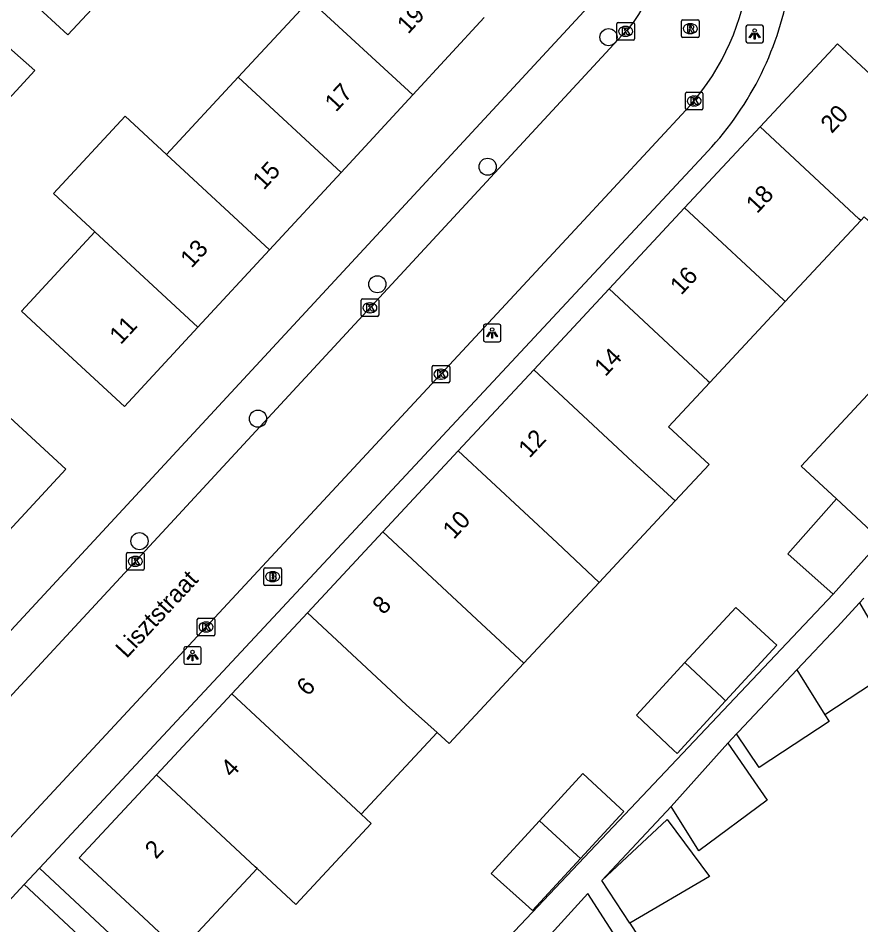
# Model space of a CAD drawing. Extents: x 159222 to 160346, y 381249 to 382166.
# Drawn here: x 159950.6 to 159998.6, y 381636 to 381687.7 of the extents above; entities that cross this region are included whole.
import ezdxf

# ---------------------------------------------------------------- set-up
doc = ezdxf.new("R2010")
doc.units = 0
for name, color, linetype in [('IMGEO_Boom', 7, 'Continuous'), ('IMGEO_Brandkraan', 7, 'Continuous'), ('IMGEO_Kolk', 7, 'Continuous'), ('IMGEO_Lichtpunt', 7, 'Continuous'), ('IMGEO_Openbare_ruimte_label', 7, 'Continuous'), ('IMGEO_Pand', 7, 'Continuous'), ('IMGEO_Pand_nummerreeks', 7, 'Continuous'), ('IMGEO_Rijbaan_lokaal_open', 7, 'Continuous'), ('IMGEO_Rioolput', 7, 'Continuous'), ('IMGEO_Voetpad_open', 7, 'Continuous')]:
    doc.layers.add(name, color=color, linetype=linetype)

msp = doc.modelspace()

# ---------------------------------------------------------------- linework, layer by layer
at = {"layer": 'IMGEO_Boom'}
for centre in [(159984.255, 381686.602), (159977.364, 381679.218), (159971.081, 381672.52), (159964.278, 381664.857), (159957.526, 381657.879)]:
    msp.add_circle(centre, 0.489, dxfattribs=at)
at = {"layer": 'IMGEO_Brandkraan'}
for p, q in [((159964.615, 381655.428), (159964.615, 381656.28)), ((159964.69, 381656.354), (159965.542, 381656.354)), ((159965.103, 381656.134), (159965.128, 381656.134)), ((159965.616, 381656.28), (159965.616, 381655.428)), ((159965.126, 381655.574), (159965.101, 381655.574)), ((159965.542, 381655.354), (159964.69, 381655.354))]:
    msp.add_line(p, q, dxfattribs=at)
for points in [[(159964.615, 381655.428), (159964.615, 381656.28)], [(159964.69, 381656.354), (159965.542, 381656.354)], [(159964.963, 381656.054), (159964.963, 381655.654), (159965.176, 381655.654)], [(159965.194, 381656.054), (159964.963, 381656.054)], [(159965.142, 381655.973), (159965.088, 381655.973), (159965.088, 381655.897)], [(159965.616, 381656.28), (159965.616, 381655.428)], [(159965.088, 381655.897), (159965.141, 381655.897)], [(159965.15, 381655.821), (159965.088, 381655.821), (159965.088, 381655.74)], [(159965.088, 381655.74), (159965.15, 381655.74)], [(159965.542, 381655.354), (159964.69, 381655.354)]]:
    msp.add_lwpolyline(points, dxfattribs=at)
for centre, radius, start, end in [((159964.692, 381656.278), 0.0765, 91.552, 178.448), ((159964.692, 381656.278), 0.0765, 91.552, 178.448), ((159965.143, 381655.935), 0.0379, 267.8285, 90.9355), ((159965.198, 381655.909), 0.145, 59.4692, 91.5367), ((159965.223, 381655.956), 0.0922, 285.5137, 58.1501), ((159965.54, 381656.278), 0.0765, 1.552, 88.448), ((159965.54, 381656.278), 0.0765, 1.552, 88.448), ((159964.692, 381655.43), 0.0765, 181.552, 268.448), ((159964.692, 381655.43), 0.0765, 181.552, 268.448), ((159965.151, 381655.78), 0.0404, 269.8759, 90.5077), ((159965.182, 381655.905), 0.251, 268.6676, 293.5347), ((159965.228, 381655.764), 0.105, 301.3115, 78.989), ((159965.54, 381655.43), 0.0765, 271.552, 358.448), ((159965.54, 381655.43), 0.0765, 271.552, 358.448)]:
    msp.add_arc(centre, radius, start, end, dxfattribs=at)
for centre, major_axis, ratio, start_param, end_param in [((159965.102, 381655.854), (-0.387, 0.002), 0.722429, 4.712389, 7.853982), ((159965.127, 381655.854), (-0.39, 0.002), 0.717154, 1.570796, 4.712389)]:
    msp.add_ellipse(centre, major_axis=major_axis, ratio=ratio, start_param=start_param, end_param=end_param, dxfattribs=at)
at = {"layer": 'IMGEO_Kolk'}
for p, q in [((159984.728, 381686.511), (159984.728, 381687.363)), ((159984.803, 381687.437), (159985.655, 381687.437)), ((159985.216, 381687.217), (159985.241, 381687.217)), ((159985.729, 381687.363), (159985.729, 381686.511)), ((159985.655, 381686.437), (159984.803, 381686.437)), ((159985.239, 381686.657), (159985.214, 381686.657)), ((159988.633, 381682.536), (159988.633, 381683.388)), ((159988.708, 381683.462), (159989.56, 381683.462)), ((159989.634, 381683.388), (159989.634, 381682.536)), ((159989.121, 381683.242), (159989.146, 381683.242)), ((159989.56, 381682.462), (159988.708, 381682.462)), ((159989.144, 381682.682), (159989.119, 381682.682)), ((159970.156, 381670.754), (159970.156, 381671.606)), ((159970.231, 381671.68), (159971.083, 381671.68)), ((159970.644, 381671.46), (159970.669, 381671.46)), ((159971.157, 381671.606), (159971.157, 381670.754)), ((159971.083, 381670.68), (159970.231, 381670.68)), ((159970.667, 381670.9), (159970.642, 381670.9)), ((159974.276, 381667.896), (159975.128, 381667.896)), ((159974.201, 381666.97), (159974.201, 381667.822)), ((159974.689, 381667.676), (159974.714, 381667.676)), ((159975.202, 381667.822), (159975.202, 381666.97)), ((159975.128, 381666.896), (159974.276, 381666.896)), ((159974.712, 381667.116), (159974.687, 381667.116)), ((159956.79, 381656.3), (159956.79, 381657.152)), ((159956.865, 381657.226), (159957.717, 381657.226)), ((159957.278, 381657.006), (159957.303, 381657.006)), ((159957.791, 381657.152), (159957.791, 381656.3)), ((159957.717, 381656.226), (159956.865, 381656.226)), ((159957.301, 381656.446), (159957.276, 381656.446)), ((159960.821, 381652.56), (159960.821, 381653.412)), ((159960.896, 381653.486), (159961.748, 381653.486)), ((159961.822, 381653.412), (159961.822, 381652.56)), ((159961.309, 381653.266), (159961.334, 381653.266)), ((159961.748, 381652.486), (159960.896, 381652.486)), ((159961.332, 381652.706), (159961.307, 381652.706))]:
    msp.add_line(p, q, dxfattribs=at)
for points in [[(159984.728, 381686.511), (159984.728, 381687.363)], [(159984.803, 381687.437), (159985.655, 381687.437)], [(159985.049, 381687.137), (159985.172, 381687.137), (159985.172, 381686.986), (159985.302, 381687.137), (159985.466, 381687.137), (159985.32, 381686.986), (159985.473, 381686.737), (159985.321, 381686.737), (159985.236, 381686.901), (159985.172, 381686.834), (159985.172, 381686.737), (159985.049, 381686.737), (159985.049, 381687.137)], [(159985.729, 381687.363), (159985.729, 381686.511)], [(159985.655, 381686.437), (159984.803, 381686.437)], [(159988.633, 381682.536), (159988.633, 381683.388)], [(159988.708, 381683.462), (159989.56, 381683.462)], [(159989.634, 381683.388), (159989.634, 381682.536)], [(159988.954, 381683.162), (159989.077, 381683.162), (159989.077, 381683.011), (159989.207, 381683.162), (159989.371, 381683.162), (159989.225, 381683.011), (159989.378, 381682.762), (159989.226, 381682.762), (159989.141, 381682.926), (159989.077, 381682.859), (159989.077, 381682.762), (159988.954, 381682.762), (159988.954, 381683.162)], [(159989.56, 381682.462), (159988.708, 381682.462)], [(159970.156, 381670.754), (159970.156, 381671.606)], [(159970.231, 381671.68), (159971.083, 381671.68)], [(159971.157, 381671.606), (159971.157, 381670.754)], [(159970.477, 381671.38), (159970.6, 381671.38), (159970.6, 381671.229), (159970.73, 381671.38), (159970.894, 381671.38), (159970.748, 381671.229), (159970.901, 381670.98), (159970.749, 381670.98), (159970.664, 381671.144), (159970.6, 381671.077), (159970.6, 381670.98), (159970.477, 381670.98), (159970.477, 381671.38)], [(159971.083, 381670.68), (159970.231, 381670.68)], [(159974.276, 381667.896), (159975.128, 381667.896)], [(159974.201, 381666.97), (159974.201, 381667.822)], [(159974.522, 381667.596), (159974.645, 381667.596), (159974.645, 381667.445), (159974.775, 381667.596), (159974.939, 381667.596), (159974.793, 381667.445), (159974.946, 381667.196), (159974.794, 381667.196), (159974.709, 381667.36), (159974.645, 381667.293), (159974.645, 381667.196), (159974.522, 381667.196), (159974.522, 381667.596)], [(159975.202, 381667.822), (159975.202, 381666.97)], [(159975.128, 381666.896), (159974.276, 381666.896)], [(159956.79, 381656.3), (159956.79, 381657.152)], [(159956.865, 381657.226), (159957.717, 381657.226)], [(159957.791, 381657.152), (159957.791, 381656.3)], [(159957.111, 381656.926), (159957.234, 381656.926), (159957.234, 381656.775), (159957.364, 381656.926), (159957.528, 381656.926), (159957.382, 381656.775), (159957.535, 381656.526), (159957.383, 381656.526), (159957.298, 381656.69), (159957.234, 381656.623), (159957.234, 381656.526), (159957.111, 381656.526), (159957.111, 381656.926)], [(159957.717, 381656.226), (159956.865, 381656.226)], [(159960.821, 381652.56), (159960.821, 381653.412)], [(159960.896, 381653.486), (159961.748, 381653.486)], [(159961.822, 381653.412), (159961.822, 381652.56)], [(159961.142, 381653.186), (159961.265, 381653.186), (159961.265, 381653.035), (159961.395, 381653.186), (159961.559, 381653.186), (159961.413, 381653.035), (159961.566, 381652.786), (159961.414, 381652.786), (159961.329, 381652.95), (159961.265, 381652.883), (159961.265, 381652.786), (159961.142, 381652.786), (159961.142, 381653.186)], [(159961.748, 381652.486), (159960.896, 381652.486)]]:
    msp.add_lwpolyline(points, dxfattribs=at)
for centre, start, end in [((159984.805, 381687.361), 91.552, 178.448), ((159984.805, 381687.361), 91.552, 178.448), ((159985.653, 381687.361), 1.552, 88.448), ((159985.653, 381687.361), 1.552, 88.448), ((159984.805, 381686.513), 181.552, 268.448), ((159984.805, 381686.513), 181.552, 268.448), ((159985.653, 381686.513), 271.552, 358.448), ((159985.653, 381686.513), 271.552, 358.448), ((159988.71, 381683.386), 91.552, 178.448), ((159988.71, 381683.386), 91.552, 178.448), ((159989.558, 381683.386), 1.552, 88.448), ((159989.558, 381683.386), 1.552, 88.448), ((159988.71, 381682.538), 181.552, 268.448), ((159988.71, 381682.538), 181.552, 268.448), ((159989.558, 381682.538), 271.552, 358.448), ((159989.558, 381682.538), 271.552, 358.448), ((159970.233, 381671.604), 91.552, 178.448), ((159970.233, 381671.604), 91.552, 178.448), ((159971.081, 381671.604), 1.552, 88.448), ((159971.081, 381671.604), 1.552, 88.448), ((159970.233, 381670.756), 181.552, 268.448), ((159970.233, 381670.756), 181.552, 268.448), ((159971.081, 381670.756), 271.552, 358.448), ((159971.081, 381670.756), 271.552, 358.448), ((159974.278, 381667.82), 91.552, 178.448), ((159974.278, 381667.82), 91.552, 178.448), ((159975.126, 381667.82), 1.552, 88.448), ((159975.126, 381667.82), 1.552, 88.448), ((159974.278, 381666.972), 181.552, 268.448), ((159974.278, 381666.972), 181.552, 268.448), ((159975.126, 381666.972), 271.552, 358.448), ((159975.126, 381666.972), 271.552, 358.448), ((159956.867, 381657.15), 91.552, 178.448), ((159956.867, 381657.15), 91.552, 178.448), ((159957.715, 381657.15), 1.552, 88.448), ((159957.715, 381657.15), 1.552, 88.448), ((159956.867, 381656.302), 181.552, 268.448), ((159956.867, 381656.302), 181.552, 268.448), ((159957.715, 381656.302), 271.552, 358.448), ((159957.715, 381656.302), 271.552, 358.448), ((159960.898, 381653.41), 91.552, 178.448), ((159960.898, 381653.41), 91.552, 178.448), ((159961.746, 381653.41), 1.552, 88.448), ((159961.746, 381653.41), 1.552, 88.448), ((159960.898, 381652.562), 181.552, 268.448), ((159960.898, 381652.562), 181.552, 268.448), ((159961.746, 381652.562), 271.552, 358.448), ((159961.746, 381652.562), 271.552, 358.448)]:
    msp.add_arc(centre, 0.0765, start, end, dxfattribs=at)
for centre, major_axis, ratio, start_param, end_param in [((159985.215, 381686.937), (-0.387, 0.002), 0.722429, 4.712389, 7.853982), ((159985.24, 381686.937), (-0.39, 0.002), 0.717154, 1.570796, 4.712389), ((159989.12, 381682.962), (-0.387, 0.002), 0.722429, 4.712389, 7.853982), ((159989.145, 381682.962), (-0.39, 0.002), 0.717154, 1.570796, 4.712389), ((159970.643, 381671.18), (-0.387, 0.002), 0.722429, 4.712389, 7.853982), ((159970.668, 381671.18), (-0.39, 0.002), 0.717154, 1.570796, 4.712389), ((159974.688, 381667.396), (-0.387, 0.002), 0.722429, 4.712389, 7.853982), ((159974.713, 381667.396), (-0.39, 0.002), 0.717154, 1.570796, 4.712389), ((159957.277, 381656.726), (-0.387, 0.002), 0.722429, 4.712389, 7.853982), ((159957.302, 381656.726), (-0.39, 0.002), 0.717154, 1.570796, 4.712389), ((159961.308, 381652.986), (-0.387, 0.002), 0.722429, 4.712389, 7.853982), ((159961.333, 381652.986), (-0.39, 0.002), 0.717154, 1.570796, 4.712389)]:
    msp.add_ellipse(centre, major_axis=major_axis, ratio=ratio, start_param=start_param, end_param=end_param, dxfattribs=at)
at = {"layer": 'IMGEO_Lichtpunt'}
for p, q in [((159992.081, 381687.188), (159992.081, 381686.381)), ((159992.081, 381687.188), (159992.081, 381686.381)), ((159992.983, 381687.283), (159992.175, 381687.283)), ((159992.983, 381687.283), (159992.175, 381687.283)), ((159993.077, 381686.381), (159993.077, 381687.188)), ((159993.077, 381686.381), (159993.077, 381687.188)), ((159992.175, 381686.287), (159992.983, 381686.287)), ((159992.175, 381686.287), (159992.983, 381686.287)), ((159977.124, 381670.146), (159977.124, 381669.339)), ((159977.124, 381670.146), (159977.124, 381669.339)), ((159978.026, 381670.241), (159977.218, 381670.241)), ((159978.026, 381670.241), (159977.218, 381670.241)), ((159978.12, 381669.339), (159978.12, 381670.146)), ((159978.12, 381669.339), (159978.12, 381670.146)), ((159977.218, 381669.245), (159978.026, 381669.245)), ((159977.218, 381669.245), (159978.026, 381669.245)), ((159960.954, 381651.855), (159960.146, 381651.855)), ((159960.954, 381651.855), (159960.146, 381651.855)), ((159960.052, 381651.76), (159960.052, 381650.953)), ((159960.052, 381651.76), (159960.052, 381650.953)), ((159961.048, 381650.953), (159961.048, 381651.76)), ((159961.048, 381650.953), (159961.048, 381651.76)), ((159960.146, 381650.859), (159960.954, 381650.859)), ((159960.146, 381650.859), (159960.954, 381650.859))]:
    msp.add_line(p, q, dxfattribs=at)
for points in [[(159992.455, 381686.852), (159992.494, 381686.824), (159992.306, 381686.562), (159992.268, 381686.589), (159992.455, 381686.852)], [(159992.557, 381686.804), (159992.604, 381686.804), (159992.604, 381686.482), (159992.557, 381686.482), (159992.557, 381686.804)], [(159992.667, 381686.824), (159992.705, 381686.851), (159992.892, 381686.589), (159992.853, 381686.561), (159992.667, 381686.824)], [(159977.498, 381669.81), (159977.537, 381669.782), (159977.349, 381669.52), (159977.311, 381669.547), (159977.498, 381669.81)], [(159977.6, 381669.762), (159977.647, 381669.762), (159977.647, 381669.44), (159977.6, 381669.44), (159977.6, 381669.762)], [(159977.71, 381669.782), (159977.748, 381669.809), (159977.935, 381669.547), (159977.896, 381669.519), (159977.71, 381669.782)], [(159960.426, 381651.424), (159960.465, 381651.396), (159960.277, 381651.134), (159960.239, 381651.161), (159960.426, 381651.424)], [(159960.528, 381651.376), (159960.575, 381651.376), (159960.575, 381651.054), (159960.528, 381651.054), (159960.528, 381651.376)], [(159960.638, 381651.396), (159960.676, 381651.423), (159960.863, 381651.161), (159960.824, 381651.133), (159960.638, 381651.396)]]:
    msp.add_lwpolyline(points, dxfattribs=at)
for centre in [(159992.58, 381686.986), (159977.623, 381669.944), (159960.551, 381651.558)]:
    msp.add_circle(centre, 0.0994, dxfattribs=at)
for centre, start, end in [((159992.175, 381687.188), 90, 180), ((159992.175, 381687.188), 90, 180), ((159992.983, 381687.188), 0, 90), ((159992.983, 381687.188), 0, 90), ((159992.175, 381686.381), 180, 270), ((159992.175, 381686.381), 180, 270), ((159992.983, 381686.381), 270, 0), ((159992.983, 381686.381), 270, 360), ((159977.218, 381670.146), 90, 180), ((159977.218, 381670.146), 90, 180), ((159978.026, 381670.146), 0, 90), ((159978.026, 381670.146), 0, 90), ((159977.218, 381669.339), 180, 270), ((159977.218, 381669.339), 180, 270), ((159978.026, 381669.339), 270, 0), ((159978.026, 381669.339), 270, 360), ((159960.146, 381651.76), 90, 180), ((159960.146, 381651.76), 90, 180), ((159960.954, 381651.76), 0, 90), ((159960.954, 381651.76), 0, 90), ((159960.146, 381650.953), 180, 270), ((159960.146, 381650.953), 180, 270), ((159960.954, 381650.953), 270, 0), ((159960.954, 381650.953), 270, 360)]:
    msp.add_arc(centre, 0.0946, start, end, dxfattribs=at)
at = {"layer": 'IMGEO_Pand'}
for points in [[(159956.721, 381690.268), (159953.445, 381686.728), (159951.342, 381688.674)], [(159963.145, 381684.326), (159967.227, 381688.738)], [(159967.227, 381688.738), (159973.094, 381683.308)], [(159973.094, 381683.308), (159977.176, 381687.719)], [(159992.885, 381681.498), (159997.292, 381686.233), (160000, 381683.713), (160000.64, 381683.117), (160004.517, 381687.283)], [(159949.417, 381686.593), (159951.569, 381684.701), (159948.558, 381681.448)], [(159959.063, 381679.915), (159963.145, 381684.326)], [(159963.145, 381684.326), (159969.013, 381678.897)], [(159973.094, 381683.308), (159969.013, 381678.897)], [(159954.981, 381675.504), (159952.624, 381677.685), (159956.706, 381682.096), (159959.063, 381679.915)], [(159988.586, 381676.88), (159992.885, 381681.498)], [(159998.622, 381676.159), (159998.515, 381676.258), (159992.885, 381681.498)], [(160010.527, 381681.481), (160006.63, 381677.295), (160005.869, 381678.004), (160001.779, 381673.614), (160000, 381675.272), (159998.82, 381676.371), (159998.622, 381676.159)], [(159964.931, 381674.486), (159959.063, 381679.915)], [(159969.013, 381678.897), (159964.931, 381674.486)], [(159984.288, 381672.262), (159988.586, 381676.88)], [(159988.586, 381676.88), (159994.216, 381671.64), (159994.324, 381671.541)], [(159998.622, 381676.159), (159994.324, 381671.541)], [(159960.849, 381670.074), (159956.667, 381665.555), (159952.997, 381668.951), (159950.799, 381670.984), (159954.981, 381675.504)], [(159960.849, 381670.074), (159954.981, 381675.504)], [(159964.931, 381674.486), (159960.849, 381670.074)], [(159979.989, 381667.644), (159984.288, 381672.262)], [(159984.288, 381672.262), (159989.918, 381667.022), (159990.025, 381666.923)], [(159994.324, 381671.541), (159990.025, 381666.923)], [(159943.281, 381662.888), (159947.462, 381667.407), (159949.654, 381665.378), (159953.324, 381661.982), (159949.141, 381657.462)], [(159975.69, 381663.025), (159979.989, 381667.644)], [(159988.05, 381660.172), (159985.62, 381662.404), (159979.989, 381667.644)], [(159990.025, 381666.923), (159987.671, 381664.394), (159989.98, 381662.245), (159988.05, 381660.172)], [(159997.247, 381660.283), (159995.229, 381662.155), (159999.513, 381666.774), (160001.531, 381664.902), (160005.087, 381661.604), (160000.803, 381656.985)], [(159971.392, 381658.407), (159975.69, 381663.025)], [(159975.69, 381663.025), (159981.321, 381657.785), (159983.727, 381655.528)], [(159988.05, 381660.172), (159983.727, 381655.528)], [(159997.054, 381654.853), (159994.464, 381657.162), (159997.247, 381660.283)], [(159999.792, 381657.923), (159997.247, 381660.283)], [(159971.392, 381658.407), (159967.094, 381653.79)], [(159979.431, 381650.915), (159977.023, 381653.167), (159971.392, 381658.407)], [(159999.792, 381657.923), (159997.054, 381654.853)], [(159983.727, 381655.528), (159979.431, 381650.915)], [(159990.925, 381648.777), (159993.841, 381651.948), (159993.638, 381652.135), (159991.502, 381654.099), (159988.606, 381650.951)], [(159998.558, 381654.364), (159997.282, 381652.982), (159994.983, 381650.543)], [(159998.558, 381654.364), (160000.622, 381650.799), (160000.69, 381650.682), (159996.58, 381647.98)], [(159962.795, 381649.172), (159967.094, 381653.79)], [(159967.094, 381653.79), (159972.725, 381648.549), (159974.491, 381646.961)], [(159974.491, 381646.961), (159975.176, 381646.344), (159979.431, 381650.915)], [(159990.925, 381648.777), (159988.164, 381645.776), (159987.962, 381645.965), (159985.846, 381647.949), (159988.606, 381650.951)], [(159988.606, 381650.951), (159990.723, 381648.966), (159990.925, 381648.777)], [(159994.983, 381650.543), (159991.653, 381647.011), (159991.537, 381646.888)], [(159994.983, 381650.543), (159996.58, 381647.98)], [(159958.497, 381644.554), (159962.795, 381649.172)], [(159962.795, 381649.172), (159968.426, 381643.931), (159970.163, 381642.312)], [(159996.58, 381647.98), (159996.818, 381647.598), (159992.837, 381644.979), (159991.537, 381646.888)], [(159974.491, 381646.961), (159970.163, 381642.312)], [(159991.049, 381646.371), (159993.293, 381643.111), (159989.403, 381640.224), (159987.82, 381642.754)], [(159987.82, 381642.754), (159991.049, 381646.371)], [(159980.318, 381641.939), (159982.79, 381644.627), (159984.914, 381642.652), (159985.117, 381642.463), (159982.657, 381639.789)], [(159964.233, 381639.216), (159959.834, 381634.49), (159957.758, 381636.422), (159954.099, 381639.829), (159958.497, 381644.554)], [(159964.233, 381639.216), (159964.128, 381639.313), (159958.497, 381644.554)], [(159970.163, 381642.312), (159970.726, 381641.788), (159966.429, 381637.172), (159964.233, 381639.216)], [(159983.878, 381638.542), (159987.594, 381642.005), (159990.012, 381638.758), (159985.466, 381636.106)], [(159982.657, 381639.789), (159979.928, 381636.822), (159979.53, 381637.177), (159977.559, 381638.939), (159980.318, 381641.939)], [(159982.657, 381639.789), (159982.453, 381639.976), (159980.318, 381641.939)], [(159985.466, 381636.106), (159983.878, 381638.542)]]:
    msp.add_lwpolyline(points, dxfattribs=at)
at = {"layer": 'IMGEO_Rijbaan_lokaal_open'}
for points in [[(159939.229, 381637.098), (159950.522, 381649.405), (159959.519, 381659.135), (159962.045, 381661.866), (159985.5, 381687.229)], [(159988.905, 381682.715), (159982.356, 381675.64), (159950.421, 381641.247), (159949.3, 381640.052), (159946.708, 381637.287), (159940.667, 381630.843)]]:
    msp.add_lwpolyline(points, dxfattribs=at)
for centre, radius, start, end in [((159980.555, 381691.266), 6.384, 320.7768, 359.41), ((159978.283, 381691.974), 14.091, 318.9212, 353.2015)]:
    msp.add_arc(centre, radius, start, end, dxfattribs=at)
at = {"layer": 'IMGEO_Rioolput'}
for p, q in [((159988.413, 381686.664), (159988.413, 381687.516)), ((159988.488, 381687.59), (159989.34, 381687.59)), ((159989.414, 381687.516), (159989.414, 381686.664)), ((159988.901, 381687.37), (159988.926, 381687.37)), ((159989.34, 381686.59), (159988.488, 381686.59)), ((159988.924, 381686.81), (159988.899, 381686.81))]:
    msp.add_line(p, q, dxfattribs=at)
for points in [[(159988.413, 381686.664), (159988.413, 381687.516)], [(159988.488, 381687.59), (159989.34, 381687.59)], [(159989.414, 381687.516), (159989.414, 381686.664)], [(159989.002, 381687.288), (159988.75, 381687.29), (159988.75, 381686.89)], [(159988.75, 381686.89), (159988.874, 381686.89), (159988.874, 381687.052), (159988.885, 381687.052)], [(159988.928, 381687.209), (159988.874, 381687.209), (159988.874, 381687.128)], [(159988.874, 381687.128), (159988.926, 381687.128)], [(159988.932, 381687.023), (159989.003, 381686.89), (159989.143, 381686.89), (159989.078, 381687.016)], [(159989.34, 381686.59), (159988.488, 381686.59)]]:
    msp.add_lwpolyline(points, dxfattribs=at)
for centre, radius, start, end in [((159988.49, 381687.514), 0.0765, 91.552, 178.448), ((159988.49, 381687.514), 0.0765, 91.552, 178.448), ((159989.338, 381687.514), 0.0765, 1.552, 88.448), ((159989.338, 381687.514), 0.0765, 1.552, 88.448), ((159988.884, 381686.999), 0.0533, 26.0293, 88.6989), ((159988.91, 381687.317), 0.19, 274.7715, 282.9687), ((159988.934, 381687.113), 0.0964, 77.0061, 93.1865), ((159988.948, 381687.17), 0.0378, 276.6634, 79.6772), ((159989.001, 381687.178), 0.109, 350.3612, 89.416), ((159988.999, 381687.178), 0.112, 277.5842, 350.9817), ((159988.983, 381686.963), 0.108, 29.5134, 73.7905), ((159988.49, 381686.666), 0.0765, 181.552, 268.448), ((159988.49, 381686.666), 0.0765, 181.552, 268.448), ((159989.338, 381686.666), 0.0765, 271.552, 358.448), ((159989.338, 381686.666), 0.0765, 271.552, 358.448)]:
    msp.add_arc(centre, radius, start, end, dxfattribs=at)
for centre, major_axis, ratio, start_param, end_param in [((159988.9, 381687.09), (-0.387, 0.002), 0.722429, 4.712389, 7.853982), ((159988.925, 381687.09), (-0.39, 0.002), 0.717154, 1.570796, 4.712389)]:
    msp.add_ellipse(centre, major_axis=major_axis, ratio=ratio, start_param=start_param, end_param=end_param, dxfattribs=at)
at = {"layer": 'IMGEO_Voetpad_open'}
for points in [[(159937.649, 381639.234), (159983.576, 381688.868)], [(159951.828, 381639.236), (159989.686, 381679.862)], [(159951.828, 381639.236), (159958.692, 381632.839), (159960.808, 381629.452), (159963.967, 381624.46), (159969.843, 381628.017), (159974.614, 381631.119), (159997.054, 381654.853)], [(159998.806, 381654.633), (159998.558, 381654.364)], [(159991.537, 381646.888), (159991.049, 381646.371)], [(159987.82, 381642.754), (159983.878, 381638.542)], [(159950.954, 381638.298), (159951.828, 381639.236)], [(159941.903, 381628.584), (159948.389, 381635.545), (159950.954, 381638.298)], [(159950.954, 381638.298), (159957.695, 381632.017), (159959.721, 381628.773)], [(159991.078, 381625.367), (159983.077, 381637.796), (159978.716, 381633.012), (159977.806, 381632.013)], [(159985.466, 381636.106), (159990.737, 381627.908)]]:
    msp.add_lwpolyline(points, dxfattribs=at)
msp.add_arc((159976.64, 381692.504), 18.166, 315.9031, 349.9104, dxfattribs=at)

# ---------------------------------------------------------------- texts
at = {"layer": 'IMGEO_Openbare_ruimte_label'}
msp.add_text('Lisztstraat', height=1, rotation=47.2291, dxfattribs=at).set_placement((159956.796, 381651.156))
at = {"layer": 'IMGEO_Pand_nummerreeks'}
for s, rotation, p in [('19', 47.2232, (159972.836, 381686.741)), ('17', 47.2215, (159968.722, 381682.294)), ('20', 47.0525, (159996.972, 381681.075)), ('15', 47.2215, (159964.607, 381677.846)), ('18', 47.0525, (159992.715, 381676.502)), ('13', 47.2215, (159960.491, 381673.399)), ('16', 47.0525, (159988.393, 381671.859)), ('11', 47.2215, (159956.453, 381669.034)), ('14', 47.0525, (159984.074, 381667.219)), ('12', 47.0525, (159979.753, 381662.575)), ('10', 47.0525, (159975.438, 381657.94)), ('8', 47.0513, (159971.433, 381653.638)), ('6', 47.0513, (159967.111, 381648.994)), ('4', 47.0525, (159962.791, 381644.354)), ('2', 47.0525, (159958.47, 381639.711))]:
    msp.add_text(s, height=1, rotation=rotation, dxfattribs=at).set_placement(p)

doc.saveas('drawing.dxf')
